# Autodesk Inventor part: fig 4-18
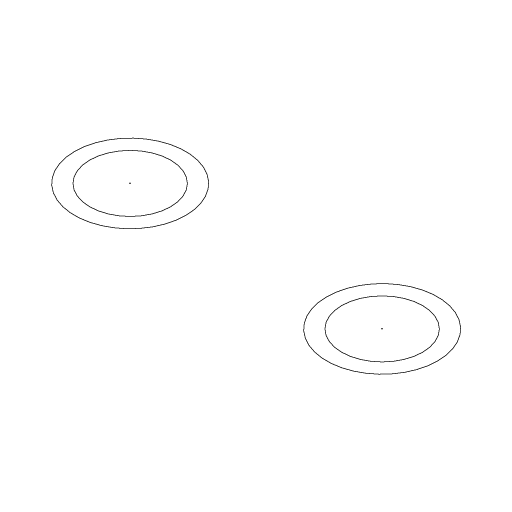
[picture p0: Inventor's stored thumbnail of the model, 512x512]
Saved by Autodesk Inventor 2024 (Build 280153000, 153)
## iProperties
Created: 2005-02
Part Number: fig 4-18
Document SubType Name: Modeling
Designer: CADCIM
Manufacturer: Standard
Standards Organization: Custom
Density: 1 g/cm^3
Material: Generic
Appearance: Default
Author: CADCIM
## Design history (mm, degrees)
sketch "Sketch1"
  geometry: C1 r 7.935 at (-23.563, 7.599); C2 r 7.935 at (12.452, 7.599); C3 r 5.782 at (-23.563, 7.599); C4 r 5.782 at (12.452, 7.599)
  constraints: 4 centre point, 1 coincident, 1 equal radius, 1 other
